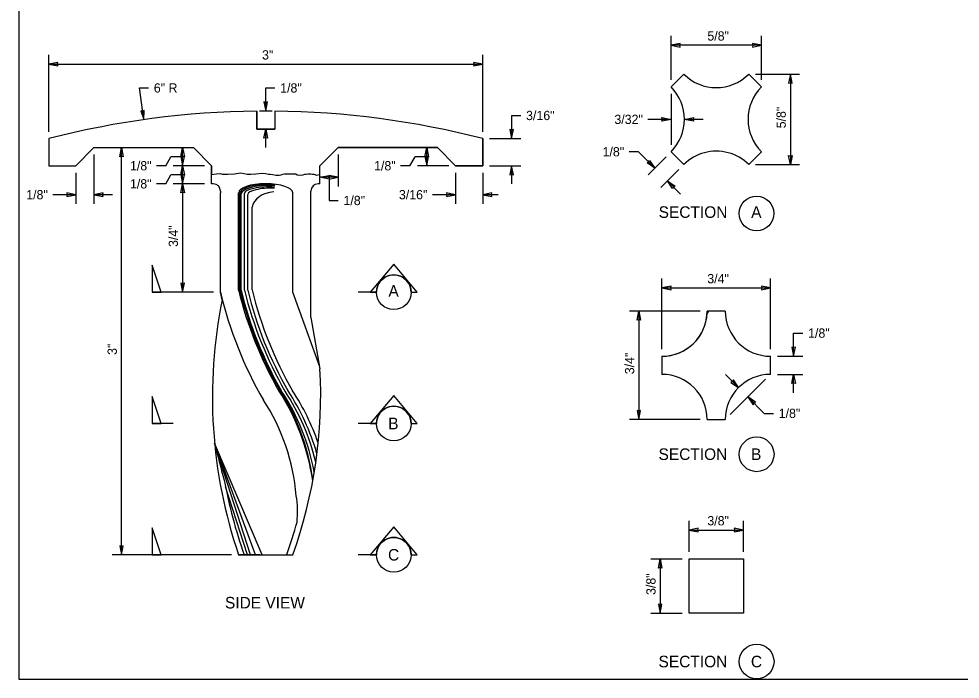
# Model space of a CAD drawing. Extents: x 99862 to 103151, y 100000 to 102076.
# Drawn here: x 99862 to 101489, y 100000 to 101141 of the extents above; entities that cross this region are included whole.
import ezdxf

# ---------------------------------------------------------------- set-up
doc = ezdxf.new("R2010")
doc.units = 0
for name, color, linetype in [('Level 1', 7, 'Continuous'), ('Level 15', 7, 'Continuous'), ('Level 20', 7, 'Continuous'), ('Level 6', 7, 'Continuous'), ('Level 60', 7, 'Continuous'), ('Level 9', 7, 'Continuous')]:
    doc.layers.add(name, color=color, linetype=linetype)

msp = doc.modelspace()

# ---------------------------------------------------------------- linework, layer by layer
at = {"layer": 'Level 1'}
msp.add_lwpolyline([(99862, 99999.5), (103151, 99999.5), (103151, 102075.5), (99862, 102075.5)], close=True, dxfattribs=at)
at = {"layer": 'Level 15'}
for p, q in [((100989.3, 101035), (100989.3, 101111.1)), ((101145.5, 101035), (101145.5, 101111.1)), ((101145.5, 101095.1), (100989.3, 101095.1)), ((99913.7, 100945.7), (99913.7, 101078.4)), ((100663.7, 100945.7), (100663.7, 101078.4)), ((99913.7, 101062.3), (100663.7, 101062.3)), ((101135.4, 101045.1), (101211.5, 101045.1)), ((101195.5, 101045.1), (101195.5, 100888.8)), ((100070.3, 101021.3), (100086.3, 101021.3)), ((100078.1, 100966.5), (100070.3, 101021.3)), ((100288.7, 100981.3), (100288.7, 101021.3)), ((100288.7, 101021.3), (100304.7, 101021.3)), ((100989.3, 101011), (100989.3, 100922.9)), ((100713.7, 100973.7), (100713.7, 100933.7)), ((100713.7, 100973.7), (100729.7, 100973.7)), ((100989.3, 100967), (100949.3, 100967)), ((101044.5, 100967), (101012.5, 100967)), ((100288.7, 100918.1), (100288.7, 100950.1)), ((100675.7, 100933.7), (100729.7, 100933.7)), ((99991.9, 100906.1), (99991.9, 100820.8)), ((100039.4, 100214.4), (100039.4, 100918.1)), ((100145, 100886.8), (100145, 100918.1)), ((100413.7, 100906.1), (100413.7, 100850.8)), ((100566.9, 100886.8), (100566.9, 100918.1)), ((100932.7, 100911), (100916.7, 100911)), ((100932.7, 100911), (100961, 100882.7)), ((100116, 100886.8), (100100, 100886.8)), ((100116, 100886.8), (100125, 100902.5)), ((100145, 100902.5), (100125, 100902.5)), ((100183, 100886.8), (100129, 100886.8)), ((100145, 100855.6), (100145, 100886.8)), ((100537.8, 100886.8), (100521.8, 100886.8)), ((100537.8, 100886.8), (100546.9, 100902.5)), ((100566.9, 100902.5), (100546.9, 100902.5)), ((100604.9, 100886.8), (100550.9, 100886.8)), ((100675.7, 100886.8), (100729.7, 100886.8)), ((100713.7, 100886.8), (100713.7, 100855.3)), ((100980.8, 100902.5), (100949.7, 100871.3)), ((101135.4, 100888.8), (101211.5, 100888.8)), ((99960.6, 100874.8), (99960.6, 100820.8)), ((100116, 100855.6), (100125, 100871.2)), ((100145, 100871.2), (100125, 100871.2)), ((100616.9, 100874.8), (100616.9, 100820.8)), ((100663.7, 100874.8), (100663.7, 100820.8)), ((101002.9, 100880.4), (100971.8, 100849.2)), ((100116, 100855.6), (100100, 100855.6)), ((100183, 100855.6), (100129, 100855.6)), ((100145, 100855.6), (100145, 100668.1)), ((100413.7, 100866.8), (100382.5, 100866.8)), ((100398.1, 100866.8), (100398.1, 100826.8)), ((100983.1, 100860.6), (101005.7, 100837.9)), ((99960.6, 100836.8), (99920.6, 100836.8)), ((100023.9, 100836.8), (99991.9, 100836.8)), ((100398.1, 100826.8), (100414.1, 100826.8)), ((100616.9, 100836.8), (100576.9, 100836.8)), ((100690.3, 100836.8), (100663.7, 100836.8)), ((100973.6, 100569.6), (100973.6, 100691.7)), ((101161.1, 100569.6), (101161.1, 100691.7)), ((100973.6, 100675.7), (101161.1, 100675.7)), ((100198.6, 100668.1), (100129, 100668.1)), ((101039.8, 100635.7), (100917.6, 100635.7)), ((100933.6, 100635.7), (100933.6, 100448.2)), ((101201.1, 100557.6), (101201.1, 100597.6)), ((101201.1, 100597.6), (101217.1, 100597.6)), ((101173.1, 100557.6), (101217.1, 100557.6)), ((101083.3, 100526.1), (101105.9, 100503.4)), ((101091.5, 100456.7), (101152.7, 100517.8)), ((101173.1, 100526.3), (101217.1, 100526.3)), ((101201.1, 100494.3), (101201.1, 100526.3)), ((101122.1, 100487.2), (101150.3, 100458.9)), ((101039.8, 100448.2), (100917.6, 100448.2)), ((101150.3, 100458.9), (101166.3, 100458.9)), ((101020.5, 100219.3), (101020.5, 100273.3)), ((101114.3, 100219.3), (101114.3, 100273.3)), ((101020.5, 100257.3), (101114.3, 100257.3)), ((100229.8, 100214.4), (100023.4, 100214.4)), ((100954.5, 100207.3), (101008.5, 100207.3)), ((100970.5, 100207.3), (100970.5, 100113.5)), ((100954.5, 100113.5), (101008.5, 100113.5))]:
    msp.add_line(p, q, dxfattribs=at)
for points in [[(100989.3, 101095.1), (101005, 101092), (101004.3, 101095.1), (101005, 101098.2)], [(101145.5, 101095.1), (101129.8, 101098.2), (101130.5, 101095.1), (101129.8, 101092)], [(99913.7, 101062.3), (99929.5, 101059.3), (99928.7, 101062.3), (99929.5, 101065.4)], [(100663.7, 101062.3), (100648, 101065.4), (100648.7, 101062.3), (100648, 101059.3)], [(101195.5, 101045.1), (101192.4, 101029.4), (101195.5, 101030.1), (101198.6, 101029.4)], [(100288.7, 100981.3), (100291.8, 100997.1), (100288.7, 100996.3), (100285.6, 100997.1)], [(100078.1, 100966.5), (100078.9, 100982.5), (100076, 100981.3), (100072.8, 100981.6)], [(100989.3, 100967), (100973.5, 100963.9), (100974.3, 100967), (100973.5, 100970.1)], [(101012.5, 100967), (101028.2, 100970.1), (101027.5, 100967), (101028.2, 100963.9)], [(100288.7, 100950.1), (100291.8, 100934.4), (100288.7, 100935.1), (100285.6, 100934.4)], [(100713.7, 100933.7), (100716.8, 100949.4), (100713.7, 100948.7), (100710.6, 100949.4)], [(100039.4, 100918.1), (100042.5, 100902.4), (100039.4, 100903.1), (100036.3, 100902.4)], [(100145, 100918.1), (100148.1, 100902.3), (100145, 100903.1), (100141.9, 100902.3)], [(100145, 100886.8), (100148.1, 100902.6), (100145, 100901.8), (100141.9, 100902.6)], [(100566.9, 100918.1), (100569.9, 100902.3), (100566.9, 100903.1), (100563.8, 100902.3)], [(100566.9, 100886.8), (100569.9, 100902.6), (100566.9, 100901.8), (100563.8, 100902.6)], [(101195.5, 100888.8), (101192.4, 100904.6), (101195.5, 100903.8), (101198.6, 100904.6)], [(100145, 100886.8), (100148.1, 100871.1), (100145, 100871.8), (100141.9, 100871.1)], [(100713.7, 100886.8), (100710.6, 100871.1), (100713.7, 100871.8), (100716.8, 100871.1)], [(100961, 100882.7), (100947.7, 100891.6), (100950.4, 100893.3), (100952, 100896)], [(100145, 100855.6), (100148.1, 100871.3), (100145, 100870.6), (100141.9, 100871.3)], [(100145, 100855.6), (100148.1, 100839.9), (100145, 100840.6), (100141.9, 100839.9)], [(100382.5, 100866.8), (100398.2, 100869.9), (100397.5, 100866.8), (100398.2, 100863.7)], [(100413.7, 100866.8), (100398, 100869.9), (100398.7, 100866.8), (100398, 100863.7)], [(100983.1, 100860.6), (100996.4, 100851.6), (100993.7, 100850), (100992, 100847.3)], [(99960.6, 100836.8), (99944.9, 100839.9), (99945.6, 100836.8), (99944.9, 100833.7)], [(99991.9, 100836.8), (100007.6, 100833.7), (100006.9, 100836.8), (100007.6, 100839.9)], [(100616.9, 100836.8), (100601.1, 100839.9), (100601.9, 100836.8), (100601.1, 100833.7)], [(100663.7, 100836.8), (100679.5, 100833.7), (100678.7, 100836.8), (100679.5, 100839.9)], [(100145, 100668.1), (100148.1, 100683.8), (100145, 100683.1), (100141.9, 100683.8)], [(100973.6, 100675.7), (100989.4, 100672.6), (100988.6, 100675.7), (100989.4, 100678.8)], [(101161.1, 100675.7), (101145.4, 100678.8), (101146.1, 100675.7), (101145.4, 100672.6)], [(100933.6, 100635.7), (100936.7, 100620), (100933.6, 100620.7), (100930.6, 100620)], [(101201.1, 100557.6), (101204.2, 100573.3), (101201.1, 100572.6), (101198, 100573.3)], [(101105.9, 100503.4), (101097, 100516.7), (101095.3, 100514), (101092.6, 100512.4)], [(101201.1, 100526.3), (101204.2, 100510.6), (101201.1, 100511.3), (101198, 100510.6)], [(101122.1, 100487.2), (101131, 100473.9), (101132.7, 100476.6), (101135.4, 100478.3)], [(100933.6, 100448.2), (100936.7, 100463.9), (100933.6, 100463.2), (100930.6, 100463.9)], [(101020.5, 100257.3), (101036.2, 100254.2), (101035.5, 100257.3), (101036.2, 100260.4)], [(101114.3, 100257.3), (101098.5, 100260.4), (101099.3, 100257.3), (101098.5, 100254.2)], [(100039.4, 100214.4), (100042.5, 100230.1), (100039.4, 100229.4), (100036.3, 100230.1)], [(100970.5, 100207.3), (100973.6, 100191.6), (100970.5, 100192.3), (100967.4, 100191.6)], [(100970.5, 100113.5), (100973.6, 100129.3), (100970.5, 100128.5), (100967.4, 100129.3)]]:
    msp.add_lwpolyline(points, close=True, dxfattribs=at)
msp.add_arc((100292.7, 99481.4), 1500, 89.7345, 90.5685, dxfattribs=at)
at = {"layer": 'Level 20'}
msp.add_circle((101137.2, 100030), 30, dxfattribs=at)
at = {"layer": 'Level 6'}
for p, q in [((100273.1, 100981.3), (100273.1, 100950.1)), ((100273.1, 100950.1), (100273.1, 100981.3)), ((100304.4, 100981.3), (100304.4, 100950.1)), ((100304.4, 100981.3), (100304.4, 100950.1)), ((100273.1, 100950.1), (100304.4, 100950.1)), ((100304.4, 100950.1), (100273.1, 100950.1)), ((99913.7, 100933.7), (99913.7, 100886.8)), ((99913.7, 100933.7), (99913.7, 100886.8)), ((100663.7, 100933.7), (100663.7, 100886.8)), ((100663.7, 100886.8), (100663.7, 100933.7)), ((99960.6, 100886.8), (99991.9, 100918.1)), ((99960.6, 100886.8), (99991.9, 100918.1)), ((99991.9, 100918.1), (100163.7, 100918.1)), ((99991.9, 100918.1), (100163.7, 100918.1)), ((100195, 100886.8), (100163.7, 100918.1)), ((100163.7, 100918.1), (100195, 100886.8)), ((100382.5, 100886.8), (100413.7, 100918.1)), ((100382.5, 100886.8), (100413.7, 100918.1)), ((100585.6, 100918.1), (100413.7, 100918.1)), ((100413.7, 100918.1), (100585.6, 100918.1)), ((100616.9, 100886.8), (100585.6, 100918.1)), ((100585.6, 100918.1), (100616.9, 100886.8)), ((99913.7, 100886.8), (99960.6, 100886.8)), ((99913.7, 100886.8), (99960.6, 100886.8)), ((100195, 100855.6), (100195, 100886.8)), ((100195, 100886.8), (100195, 100871.9)), ((100382.5, 100855.6), (100382.5, 100886.8)), ((100382.5, 100871.9), (100382.5, 100886.8)), ((100663.7, 100886.8), (100616.9, 100886.8)), ((100616.9, 100886.8), (100663.7, 100886.8)), ((100198.1, 100855.6), (100195, 100855.6)), ((100382.5, 100855.6), (100379.3, 100855.6)), ((100210.6, 100843.1), (100210.6, 100840)), ((100241.8, 100671.9), (100241.8, 100840)), ((100244.2, 100671.9), (100244.2, 100839.1)), ((100246.2, 100671.9), (100246.2, 100838.4)), ((100252.1, 100671.9), (100252.1, 100838.9)), ((100335.6, 100668.1), (100335.6, 100840)), ((100366.8, 100840), (100366.8, 100843.1)), ((100366.8, 100668.1), (100366.8, 100840)), ((100257.6, 100671.9), (100257.6, 100836.8)), ((100265.3, 100672.2), (100265.3, 100815.1)), ((100382.3, 100539.5), (100335.6, 100668.1)), ((100366.8, 100624.5), (100366.8, 100668.1)), ((101051.5, 100631.6), (101053.9, 100635.7)), ((101053.9, 100635.7), (101051.7, 100631.9)), ((100366.8, 100624.5), (100382.5, 100536.1)), ((100262.3, 100214.4), (100200.4, 100407.5)), ((100282.8, 100214.4), (100200.4, 100407.5)), ((100271.2, 100214.4), (100200.4, 100407.3)), ((100257, 100214.4), (100219.2, 100332)), ((100241.8, 100214.4), (100335.6, 100214.4)), ((100279.3, 100214.4), (100241.8, 100214.4)), ((100268.7, 100214.4), (100241.8, 100214.4)), ((100255.8, 100214.4), (100241.8, 100214.4))]:
    msp.add_line(p, q, dxfattribs=at)
for points in [[(101011.4, 101045.1), (100989.3, 101023)], [(101011.4, 101045.1), (100989.3, 101023)], [(101145.5, 101023), (101123.4, 101045.1)], [(101145.5, 101023), (101123.4, 101045.1)], [(100989.3, 100910.9), (101011.4, 100888.9)], [(100989.3, 100910.9), (101011.4, 100888.9)], [(101123.4, 100888.9), (101145.5, 100910.9)], [(101123.4, 100888.9), (101145.5, 100910.9)], [(100195, 100871.9), (100203.6, 100873.1), (100209.7, 100873.3), (100214, 100872.5), (100218.5, 100872.3), (100223.4, 100872), (100234.7, 100873.1), (100245, 100874.4), (100251.5, 100873.3), (100256.4, 100872), (100262.8, 100872), (100271.4, 100873.1), (100282.5, 100873.9), (100288.1, 100873.3), (100293.4, 100872.5), (100296.2, 100872), (100300.9, 100871.6), (100306.2, 100870.4), (100311.8, 100870.6), (100315.4, 100870.9), (100318.5, 100872.2), (100321.2, 100872.9), (100327.1, 100873.1), (100332.8, 100872.6), (100340.6, 100872.6), (100343.1, 100871.1), (100348.2, 100870.6), (100353.7, 100871.1), (100356.4, 100872), (100358.6, 100872.5), (100362.2, 100872.9), (100366.5, 100872.6), (100369.5, 100872.5), (100372.1, 100872), (100376.5, 100870.8), (100379, 100871.1), (100381.7, 100871.7), (100382.5, 100871.9)], [(100195, 100871.9), (100203.6, 100873.1), (100209.7, 100873.3), (100214, 100872.5), (100218.5, 100872.3), (100223.4, 100872), (100234.7, 100873.1), (100245, 100874.4), (100251.5, 100873.3), (100256.4, 100872), (100262.8, 100872), (100271.4, 100873.1), (100282.5, 100873.9), (100288.1, 100873.3), (100293.4, 100872.5), (100296.2, 100872), (100300.9, 100871.6), (100306.2, 100870.4), (100311.8, 100870.6), (100315.4, 100870.9), (100318.5, 100872.2), (100321.2, 100872.9), (100327.1, 100873.1), (100332.8, 100872.6), (100340.6, 100872.6), (100343.1, 100871.1), (100348.2, 100870.6)], [(100348.2, 100870.6), (100353.7, 100871.1), (100356.4, 100872), (100358.6, 100872.5), (100362.2, 100872.9), (100366.5, 100872.6), (100369.5, 100872.5), (100372.1, 100872), (100376.5, 100870.8), (100379, 100871.1), (100381.7, 100871.7), (100382.5, 100871.9)], [(100213.6, 100655.3), (100210.6, 100668.1), (100210.6, 100839.8)], [(101083, 100635.7), (101051.8, 100635.7)], [(101083, 100635.7), (101053.9, 100635.7)], [(100973.6, 100557.6), (100973.6, 100526.3)], [(100973.6, 100557.6), (100973.6, 100526.3)], [(101161.1, 100526.3), (101161.1, 100557.6)], [(101161.1, 100526.3), (101161.1, 100557.6)], [(101051.8, 100448.2), (101083, 100448.2)], [(101051.8, 100448.2), (101083, 100448.2)]]:
    msp.add_lwpolyline(points, dxfattribs=at)
msp.add_lwpolyline([(101020.5, 100207.3), (101114.3, 100207.3), (101114.3, 100113.5), (101020.5, 100113.5)], close=True, dxfattribs=at)
for centre, radius, start, end in [((101067.4, 101101.1), 79.2, 225, 315), ((101067.4, 101101.1), 79.2, 225, 315), ((100933.2, 100967), 79.2, 315, 45), ((100933.2, 100967), 79.2, 315, 45), ((101201.5, 100967), 79.2, 135, 225), ((101201.5, 100967), 79.2, 135, 225), ((100288.7, 99481.3), 1500, 90.5968, 104.4775), ((100288.7, 99481.3), 1500, 90.5968, 104.4775), ((100288.7, 99481.3), 1500, 75.5225, 89.4032), ((100288.7, 99481.3), 1500, 75.5225, 89.4032), ((101067.4, 100832.8), 79.2, 75, 135), ((101067.4, 100832.8), 79.2, 75, 135), ((101067.4, 100832.8), 79.2, 45, 75), ((101067.4, 100832.8), 79.2, 45, 75), ((100198.1, 100843.1), 12.5, 0, 90), ((100379.3, 100843.1), 12.5, 90, 180), ((100881.8, 100827.2), 689.8, 193.3321, 210.0385), ((100881.8, 100827.2), 658.6, 193.6462, 210.0385), ((100884.2, 100827.2), 658.6, 193.6462, 209.5516), ((100886.2, 100827.2), 658.6, 193.6462, 210.0385), ((100892.1, 100827.2), 658.6, 193.6462, 210.0385), ((100897.6, 100827.2), 658.6, 193.6462, 210.0385), ((100905.3, 100827.5), 658.6, 193.6462, 210.0385), ((101042.7, 100487.1), 846.1, 168.534, 198.8057), ((100973.6, 100635.7), 78.1, 270, 0), ((100973.6, 100635.7), 78.1, 270, 357.224), ((101161.1, 100635.7), 78.1, 180, 270), ((101161.1, 100635.7), 78.1, 180, 270), ((99558.1, 100491.9), 825.6, 340.3543, 3.0662), ((100973.6, 100448.2), 78.1, 0, 90), ((100973.6, 100448.2), 78.1, 0.0001, 90), ((101161.1, 100448.2), 78.1, 90, 180), ((101161.1, 100448.2), 78.1, 90, 180), ((99988.4, 100287.5), 385.5, 8.2071, 33.2699), ((99988.4, 100291.6), 385.5, 7.863, 33.1371), ((99992.5, 100285.2), 387, 10.8027, 33.2699), ((99994.2, 100282.4), 392.1, 13.6132, 33.2699), ((99995.3, 100279.6), 397.3, 16.0122, 33.2699), ((99997.8, 100276.4), 403.5, 18.984, 33.2699), ((99988.4, 100287.5), 354.3, 4.7012, 33.2699), ((101967.6, 100831.4), 1817.4, 193.489, 195.5714), ((101059.4, 100498.6), 856.5, 190.4244, 199.3825), ((100160, 100288.3), 183.7, 354.6079, 8.8506), ((99547.6, 100492.6), 825.6, 340.3543, 344.4351)]:
    msp.add_arc(centre, radius, start, end, dxfattribs=at)
for centre, major_axis, ratio, start_param, end_param in [((100288.7, 100840), (-46.7, 0), 0.338163, 3.141593, 6.283185), ((100290.9, 100838.6), (-46.7, 0), 0.338163, 4.405759, 6.250518), ((100292.8, 100837), (-46.7, 0), 0.338163, 4.462141, 6.195109), ((100294.5, 100838.9), (-42.3, 0), 0.268149, 4.488689, 6.283185), ((100300, 100836.9), (-42.3, 0), 0.268149, 4.623628, 6.283185), ((100307.3, 100811.8), (-42.3, 0), 0.71192, 4.822943, 6.176433)]:
    msp.add_ellipse(centre, major_axis=major_axis, ratio=ratio, start_param=start_param, end_param=end_param, dxfattribs=at)
at = {"layer": 'Level 60'}
msp.add_line((99862, 99999.5), (99862, 99999.5), dxfattribs=at)
at = {"layer": 'Level 9'}
for p, q in [((100510, 100716.6), (100469.4, 100668.1)), ((100550.6, 100668.1), (100510, 100716.6)), ((100129, 100668.1), (100092.5, 100668.1)), ((100478.5, 100668.1), (100448.5, 100668.1)), ((100469.4, 100668.1), (100480, 100668.1)), ((100540, 100668.1), (100550.6, 100668.1)), ((100510, 100489.7), (100469.4, 100441.2)), ((100550.6, 100441.2), (100510, 100489.7)), ((100129, 100441.2), (100092.5, 100441.2)), ((100478.5, 100441.2), (100448.5, 100441.2)), ((100469.4, 100441.2), (100480, 100441.2)), ((100540, 100441.2), (100550.6, 100441.2)), ((100510, 100262.8), (100469.4, 100214.4)), ((100550.6, 100214.4), (100510, 100262.8)), ((100129, 100214.4), (100092.5, 100214.4)), ((100478.5, 100214.4), (100448.5, 100214.4)), ((100469.4, 100214.4), (100480, 100214.4)), ((100540, 100214.4), (100550.6, 100214.4))]:
    msp.add_line(p, q, dxfattribs=at)
for points in [[(100108, 100668.1), (100092.5, 100715), (100092.5, 100668.1)], [(100108, 100441.2), (100092.5, 100488.1), (100092.5, 100441.2)], [(100108, 100214.4), (100092.5, 100261.3), (100092.5, 100214.4)]]:
    msp.add_lwpolyline(points, close=True, dxfattribs=at)
for centre in [(101137, 100804.3), (100510, 100668.1), (100510, 100441.2), (101137.2, 100388.1), (100510, 100214.4)]:
    msp.add_circle(centre, 30, dxfattribs=at)
for centre in [(100510, 100668.1), (100510, 100441.2), (100510, 100214.4)]:
    msp.add_arc(centre, 30, 359.9978, 180.0022, dxfattribs=at)

# ---------------------------------------------------------------- texts
at = {"layer": 'Level 20'}
for s, height, p in [('5/8"', 16, (101052, 101103.1)), ('3"', 16, (100282.4, 101070.4)), ('6" R', 16, (100095.3, 101013.3)), ('1/8"', 16, (100313.7, 101013.3)), ('3/16"', 16, (100738.7, 100965.7)), ('3/32"', 16, (100891.3, 100959)), ('1/8"', 16, (100870.9, 100903)), ('1/8"', 16, (100054.1, 100878.8)), ('1/8"', 16, (100476, 100878.8)), ('1/8"', 16, (100054.1, 100847.6)), ('1/8"', 16, (99874.8, 100828.8)), ('3/16"', 16, (100518.9, 100828.8)), ('1/8"', 16, (100423.1, 100818.8)), ('SECTION', 20, (100967.8, 100796.7)), ('A', 20, (101127.7, 100796.7)), ('3/4"', 16, (101051.9, 100683.7)), ('A', 20, (100500.8, 100660.5)), ('1/8"', 16, (101226.1, 100589.6)), ('1/8"', 16, (101175.3, 100450.9)), ('B', 20, (100500.4, 100431.4)), ('SECTION', 20, (100967.6, 100378.3)), ('B', 20, (101127.5, 100378.3)), ('3/8"', 16, (101052, 100265.3)), ('C', 20, (100500.1, 100204.4)), ('SIDE VIEW', 20, (100218.3, 100121.7)), ('SECTION', 20, (100967.6, 100020)), ('C', 20, (101127.3, 100020))]:
    msp.add_text(s, height=height, dxfattribs=at).set_placement(p)
for s, p in [('5/8"', (101187.5, 100951.5)), ('3/4"', (100137, 100746.4)), ('3"', (100031.4, 100559.9)), ('3/4"', (100925.6, 100526.5)), ('3/8"', (100962.5, 100145))]:
    msp.add_text(s, height=16, rotation=90, dxfattribs=at).set_placement(p)

doc.saveas('drawing.dxf')
